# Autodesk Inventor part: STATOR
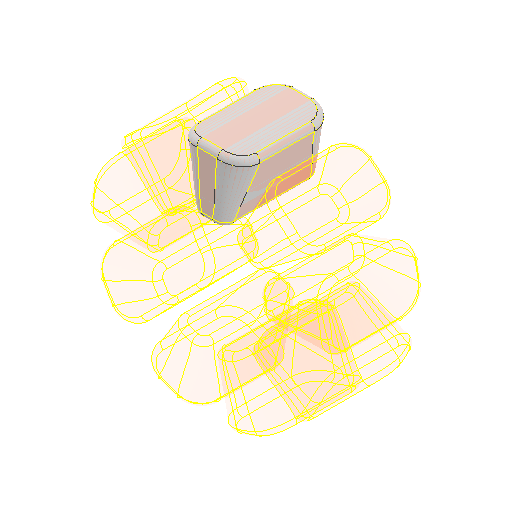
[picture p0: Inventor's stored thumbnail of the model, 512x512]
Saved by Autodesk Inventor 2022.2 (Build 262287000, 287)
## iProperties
Created: 2025-01
Part Number: STATOR
Material: Generico
Document SubType Name: Modeling
Designer: 18907419
Density: 1 g/cm^3
Appearance: Default
Author: 18907419
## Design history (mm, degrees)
feature "STATOR"
feature "Composto1"
node "Solido1"
node "Superf1"
